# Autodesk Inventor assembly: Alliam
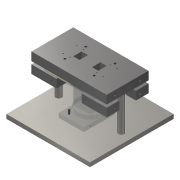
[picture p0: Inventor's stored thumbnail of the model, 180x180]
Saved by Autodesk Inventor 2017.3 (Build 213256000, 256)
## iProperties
Part Number: Alliam
Material: 一般
Document SubType Name: Assembly
Designer: kyushu-hep
Author: kyushu-hep
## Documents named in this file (11)
- E:\PixelAssembly\FlexAssembly3\Alliam.iam
- E:\PixelAssembly\FlexAssembly3\FlexBase.ipt
- E:\PixelAssembly\FlexAssembly3\ModuleBase.ipt
- E:\PixelAssembly\FlexAssembly3\Module.ipt
- E:\PixelAssembly\FlexAssembly3\FPC2.ipt
- E:\PixelAssembly\FlexAssembly3\base1.ipt
- E:\PixelAssembly\FlexAssembly3\ClearBoard.ipt
- E:\PixelAssembly\FlexAssembly3\Stages.ipt
- E:\PixelAssembly\FlexAssembly3\StagePin.ipt
- E:\PixelAssembly\FlexAssembly3\BasePin.ipt
- E:\PixelAssembly\FlexAssembly3\FlexPin.ipt
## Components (16 placed, 10 different names)
1. FlexBase:1 — メイト:32, メイト:33, メイト:34, メイト:35, メイト:36, メイト:37, メイト:38, 挿入:5, 挿入:6
2. base1:1 — メイト:13, メイト:14, メイト:26, メイト:27, メイト:28, メイト:32, メイト:33
3. FPC2:1 — メイト:23, メイト:36, メイト:37
4. ModuleBase:1 — メイト:15, メイト:16, メイト:17, メイト:47, メイト:48, メイト:49
5. Module:1 — メイト:15, メイト:16, メイト:17
6. ClearBoard:1 — メイト:23, メイト:34, メイト:35, メイト:38
7. Stages:1 — メイト:26, メイト:27, メイト:28, メイト:39, メイト:40, メイト:41, メイト:42, メイト:43, メイト:44, メイト:45, メイト:46, メイト:49, 挿入:2, 挿入:3, 挿入:4
8. StagePin:1 — メイト:39, メイト:45, メイト:47
9. StagePin:2 — メイト:40, メイト:46, メイト:48
10. StagePin:3 — メイト:41, メイト:44
11. StagePin:4 — メイト:42, メイト:43
12. BasePin:1 — 挿入:3
13. BasePin:2 — 挿入:4
14. BasePin:3 — 挿入:2
15. FlexPin:1 — 挿入:5
16. FlexPin:2 — 挿入:6
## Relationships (32: Mate 27, Insert 5)
- メイト:13 [Mate]: base1:1
- メイト:14 [Mate]: base1:1
- メイト:15 [Mate]: ModuleBase:1 ↔ Module:1
- メイト:16 [Mate]: ModuleBase:1 ↔ Module:1
- メイト:17 [Mate]: ModuleBase:1 ↔ Module:1
- メイト:23 [Mate]: FPC2:1 ↔ ClearBoard:1
- メイト:26 [Mate]: base1:1 ↔ Stages:1
- メイト:27 [Mate]: base1:1 ↔ Stages:1
- メイト:28 [Mate]: base1:1 ↔ Stages:1
- メイト:32 [Mate]: FlexBase:1 ↔ base1:1
- メイト:33 [Mate]: FlexBase:1 ↔ base1:1
- メイト:34 [Mate]: FlexBase:1 ↔ ClearBoard:1
- メイト:35 [Mate]: FlexBase:1 ↔ ClearBoard:1
- メイト:36 [Mate]: FlexBase:1 ↔ FPC2:1
- メイト:37 [Mate]: FlexBase:1 ↔ FPC2:1
- メイト:38 [Mate]: FlexBase:1 ↔ ClearBoard:1
- メイト:39 [Mate]: Stages:1 ↔ StagePin:1
- メイト:40 [Mate]: Stages:1 ↔ StagePin:2
- メイト:41 [Mate]: Stages:1 ↔ StagePin:3
- メイト:42 [Mate]: Stages:1 ↔ StagePin:4
- メイト:43 [Mate]: Stages:1 ↔ StagePin:4
- メイト:44 [Mate]: Stages:1 ↔ StagePin:3
- メイト:45 [Mate]: Stages:1 ↔ StagePin:1
- メイト:46 [Mate]: Stages:1 ↔ StagePin:2
- メイト:47 [Mate]: ModuleBase:1 ↔ StagePin:1
- メイト:48 [Mate]: ModuleBase:1 ↔ StagePin:2
- メイト:49 [Mate]: ModuleBase:1 ↔ Stages:1
- 挿入:2 [Insert]: Stages:1 ↔ BasePin:3
- 挿入:3 [Insert]: Stages:1 ↔ BasePin:1
- 挿入:4 [Insert]: Stages:1 ↔ BasePin:2
- 挿入:5 [Insert]: FlexBase:1 ↔ FlexPin:1
- 挿入:6 [Insert]: FlexBase:1 ↔ FlexPin:2
